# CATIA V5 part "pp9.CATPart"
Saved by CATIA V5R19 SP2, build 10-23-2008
Part number: pp9
Publications: "Length.1", "Length.2", "Length.3", "Length.4", "Length.5", "Length.6", "Length.7", "Length.8", "Length.9"
Bounding box of the stored display mesh (mm): x -18 to 18.012, y -108.377 to 108.377, z 34.141 to 67.984
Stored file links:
  C:\Users\Welcome\Documents\thinkm2\pp9.CATPart
  C:\Users\Welcome\Documents\thinkm2\Brasmeca.CATProduct
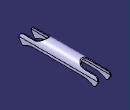
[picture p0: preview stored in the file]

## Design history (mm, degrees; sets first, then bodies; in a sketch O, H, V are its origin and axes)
Parameters
  LENGTH = 16 mm
  LENGTH = 18 mm
  LENGTH = 36 mm
  LENGTH = 32 mm
  LENGTH = 17.604 mm
  LENGTH = 1.601 mm
  LENGTH = 8.799 mm
  LENGTH = 6.95 mm
  LENGTH = 1.745 mm
AxisSystem1: origin (0, 0, 0), X (1, 0, 0), Y (0, 1, 0), Z (0, 0, 1)
Set1
  Line1: linked copy from another document
  Point1: linked copy from another document
  Plane1: linked copy from another document
  Line2: linked copy from another document
Body1 (main body)
  Sketch1 on Plane1, origin (0, -110, 0), H (-1, 0, 0), V (0, 0, 1)
    arc A1 centre (0, 50) radius 16 from (16, 50) to (-16, 49.9871) ccw
    arc A2 centre (0, 50) radius 18 from (18, 50.0003) to (-18, 50.0141) ccw
    reference projected point E1 (0, 50) from Line2
    reference projected point E2 (0, 50) from Line2
    line L1 (-16, 49.9871) -> (-15.9858, 32.3548)
    line L2 (-18, 50.0141) -> (-18.0138, 32.3532)
    line L3 (-15.9858, 32.3548) -> (-18.0138, 32.3532)
    line L4 (18, 50.0003) -> (18, 32.3963)
    line L5 (16, 50) -> (16, 32.3946)
    line L6 (18, 32.3963) -> (16, 32.3946)
    distance A2 E1 = 18 {= LENGTH}
    distance A1 E2 = 16 {= LENGTH}
    radius A2 = 18 {= LENGTH /2}
    radius A1 = 16 {= LENGTH /2}
    length L4 = 17.604 {= LENGTH}
  Pad1: profile Sketch1, direction (0, 1, 0), length 220
  Sketch2 on face of Pad1 from Sketch1.L4, origin (-18, 0, 0), H (0, -1, 0), V (0, 0, 1)
    line L1 (42.6272, 70.3947) -> (54.1435, 63.1792)
    line L2 (69.3833, 58.7993) -> (99.5172, 58.7993)
    line L3 (106.7317, 54.0009) -> (107.8804, 51.2601)
    line L4 (107.3808, 45.1379) -> (101.9614, 36.4883)
    line L5 (97.7204, 34.1413) -> (95.8992, 34.1413)
    line L6 (95.8992, 34.1413) -> (87.2407, 38.514)
    line L7 (68.1931, 43.0503) -> (9.0727, 43.0503)
    arc A1 centre (69.3833, 87.5028) radius 28.7035 from (54.1435, 63.1792) to (69.3833, 58.7993) ccw
    arc A2 centre (99.5176, 50.9771) radius 7.8221 from (99.5172, 58.7993) to (106.7317, 54.0009) cw
    arc A3 centre (101.7261, 48.6808) radius 6.6729 from (107.8804, 51.2601) to (107.3808, 45.1379) cw
    arc A4 centre (97.7209, 39.1456) radius 5.0043 from (101.9614, 36.4883) to (97.7204, 34.1413) cw
    arc A5 centre (68.1943, 0.797) radius 42.2532 from (87.2407, 38.514) to (68.1931, 43.0503) ccw
    line L8 (-42.6272, 70.3946) -> (-54.1435, 63.1791)
    arc A6 centre (-69.3833, 87.5027) radius 28.7035 from (-54.1435, 63.1791) to (-69.3833, 58.7992) cw
    line L9 (-69.3833, 58.7992) -> (-99.5172, 58.7992)
    arc A7 centre (-99.5172, 50.9771) radius 7.8221 from (-99.5172, 58.7992) to (-106.7314, 54.0006) ccw
    line L10 (-106.7314, 54.0006) -> (-107.8801, 51.2597)
    arc A8 centre (-101.7258, 48.6805) radius 6.6729 from (-107.8801, 51.2597) to (-107.3805, 45.1376) ccw
    line L11 (-107.3805, 45.1376) -> (-101.9611, 36.488)
    arc A9 centre (-97.7204, 39.145) radius 5.0043 from (-101.9611, 36.488) to (-97.7204, 34.1406) ccw
    line L12 (-95.8992, 34.1406) -> (-87.2407, 38.5134)
    arc A10 centre (-68.1931, 0.797) radius 42.2532 from (-87.2407, 38.5134) to (-68.1931, 43.0503) cw
    line L13 (-68.1931, 43.0503) -> (-9.0727, 43.0503)
    line L14 (-9.0727, 43.0503) -> (9.0727, 43.0503)
    line L15 (42.6272, 70.3947) -> (119.6154, 70.3947)
    line L16 (119.6154, 70.3947) -> (119.6154, 25.4267)
    line L17 (119.6154, 25.4267) -> (-119.5698, 22.1865)
    line L18 (-119.5698, 22.1865) -> (-118.0658, 78.033)
    line L19 (-118.0658, 78.033) -> (-42.6272, 70.3946)
    line L20 (-97.7204, 34.1406) -> (-95.8992, 34.1406)
    arc A11 centre (-68.1931, -0.7974) radius 42.2532 from (-87.2407, -38.5137) to (-68.1931, -43.0506) ccw
    line L21 (-95.8992, -34.141) -> (-87.2407, -38.5137)
    line L22 (-97.7204, -34.141) -> (-95.8992, -34.141)
    arc A12 centre (-97.7204, -39.1453) radius 5.0043 from (-101.9611, -36.4883) to (-97.7204, -34.141) cw
    line L23 (-107.3805, -45.1379) -> (-101.9611, -36.4883)
    arc A13 centre (-101.7258, -48.6808) radius 6.6729 from (-107.8801, -51.2601) to (-107.3805, -45.1379) cw
    line L24 (-106.7314, -54.0009) -> (-107.8801, -51.2601)
    arc A14 centre (-99.5172, -50.9775) radius 7.8221 from (-99.5172, -58.7996) to (-106.7314, -54.0009) cw
    line L25 (-69.3833, -58.7996) -> (-99.5172, -58.7996)
    arc A15 centre (-69.3833, -87.5031) radius 28.7035 from (-54.1435, -63.1795) to (-69.3833, -58.7996) ccw
    line L26 (-42.6272, -70.395) -> (-54.1435, -63.1795)
    line L27 (-118.0658, -78.0334) -> (-42.6272, -70.395)
    line L28 (-119.5698, -22.1868) -> (-118.0658, -78.0334)
    line L29 (119.6154, -25.427) -> (-119.5698, -22.1868)
    line L30 (-68.1931, -43.0506) -> (-9.0727, -43.0506)
    line L31 (-9.0727, -43.0506) -> (9.0727, -43.0506)
    line L32 (68.1931, -43.0506) -> (9.0727, -43.0506)
    arc A16 centre (68.1931, -0.7974) radius 42.2532 from (87.2407, -38.5137) to (68.1931, -43.0506) cw
    line L33 (95.8992, -34.141) -> (87.2407, -38.5137)
    line L34 (97.7204, -34.141) -> (95.8992, -34.141)
    arc A17 centre (97.7204, -39.1453) radius 5.0043 from (101.9611, -36.4883) to (97.7204, -34.141) ccw
    line L35 (107.3805, -45.1379) -> (101.9611, -36.4883)
    arc A18 centre (101.7258, -48.6808) radius 6.6729 from (107.8801, -51.2601) to (107.3805, -45.1379) ccw
    line L36 (106.7314, -54.0009) -> (107.8801, -51.2601)
    arc A19 centre (99.5172, -50.9775) radius 7.8221 from (99.5172, -58.7996) to (106.7314, -54.0009) ccw
    line L37 (69.3833, -58.7996) -> (99.5172, -58.7996)
    arc A20 centre (69.3833, -87.5031) radius 28.7035 from (54.1435, -63.1795) to (69.3833, -58.7996) cw
    line L38 (42.6272, -70.395) -> (54.1435, -63.1795)
    line L39 (42.6272, -70.395) -> (119.6154, -70.395)
    line L40 (119.6154, -70.395) -> (119.6154, -25.427)
    reference projected line E1 (110, 50.0003) -> (-110, 50.0003) from edge [face of Pad1 from Sketch1.A2 | face of Pad1 from Sketch1.L4]
    reference projected line E2 (110, 50.0003) -> (-110, 50.0003) from edge [face of Pad1 from Sketch1.A2 | face of Pad1 from Sketch1.L4]
    reference projected line E3 (110, 32.3963) -> (-110, 32.3963) from edge [face of Pad1 from Sketch1.L4 | face of Pad1 from Sketch1.L6]
    reference projected line E4 (110, 32.3963) -> (110, 50.0003) from edge [start face of Pad1 | face of Pad1 from Sketch1.L4]
    distance L2 E1 = 8.799 {= LENGTH}
    distance L7 E2 = 6.95 {= LENGTH}
    distance L5 E3 = 1.745 {= LENGTH}
    distance A3 E4 = 1.601 {= LENGTH}
  Pocket1: profile Sketch2, direction (1, 0, 0), length 220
